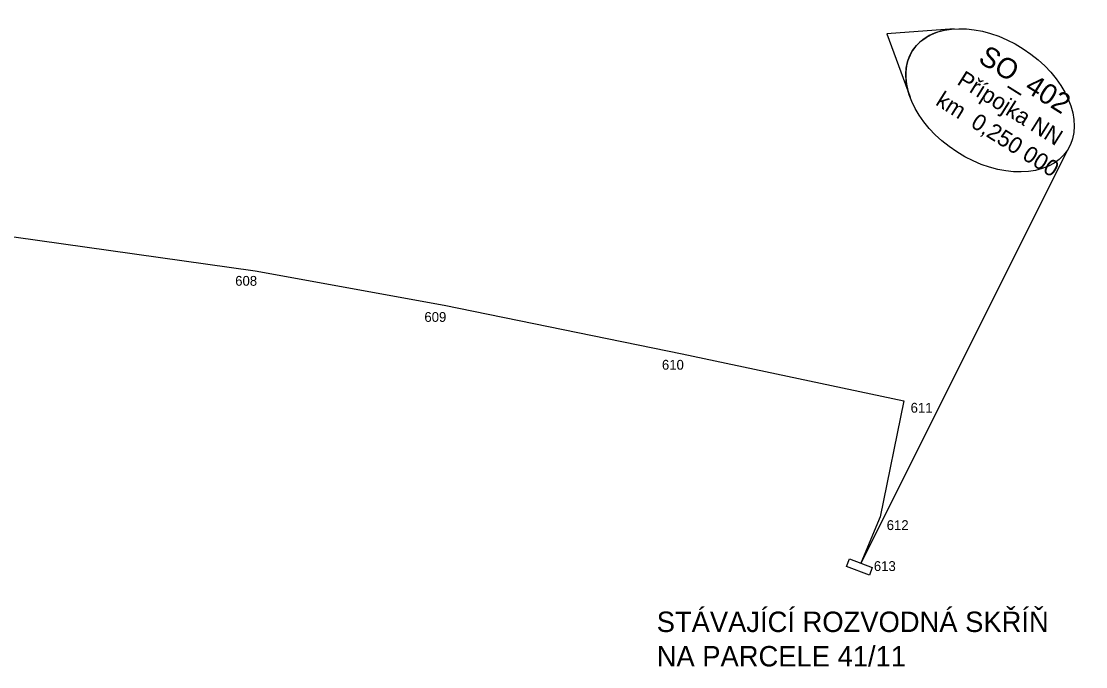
# Model space of a CAD drawing. Extents: x -743546 to -74, y -1128126 to -103.
# Drawn here: x -743045.6 to -742915.5, y -1127159.1 to -1127080.1 of the extents above; entities that cross this region are included whole.
import ezdxf

# ---------------------------------------------------------------- set-up
doc = ezdxf.new("R2010")
doc.units = 0
for name, color, linetype in [('_Násyp', 7, 'Continuous'), ('_TRASA_vedení kabelu_CEZ', 7, 'Continuous'), ('bublina_růžová_230_čára_tenká', 7, 'Continuous'), ('bublina_růžová_230_čára_tučná', 7, 'Continuous'), ('křížky', 7, 'Continuous'), ('Vrstva 60', 7, 'Continuous')]:
    doc.layers.add(name, color=color, linetype=linetype)

# ---------------------------------------------------------------- blocks, each defined once
blk = doc.blocks.new('POINT_DISPLAY')
blk.add_line((0, 0), (0, 0))

msp = doc.modelspace()

# ---------------------------------------------------------------- linework, layer by layer
at = {"layer": '_TRASA_vedení kabelu_CEZ'}
msp.add_lwpolyline([(-743154.26, -1127082.61), (-743159.25, -1127091.79), (-743078.98, -1127101.9), (-743017.04, -1127110.61), (-742993.93, -1127114.82), (-742964.82, -1127120.76), (-742937.74, -1127126.54), (-742940.65, -1127140.7), (-742943, -1127146.4)], dxfattribs=at)
msp.add_lwpolyline([(-742944.4, -1127145.87), (-742941.59, -1127146.92), (-742941.94, -1127147.86), (-742944.75, -1127146.81)], close=True, dxfattribs=at)
at = {"layer": 'bublina_růžová_230_čára_tenká'}
msp.add_line((-742917.74, -1127095.83), (-742943, -1127146.4), dxfattribs=at)
at = {"layer": 'bublina_růžová_230_čára_tučná'}
for p, q in [((-742931.59, -1127081.01), (-742939.82, -1127081.63)), ((-742931.59, -1127081.01), (-742939.82, -1127081.63)), ((-742939.82, -1127081.63), (-742936.98, -1127089.38)), ((-742939.82, -1127081.63), (-742936.98, -1127089.38))]:
    msp.add_line(p, q, dxfattribs=at)
msp.add_ellipse((-742927.2, -1127089.75), major_axis=(9.46, -6.09), ratio=0.666667, dxfattribs=at)
msp.add_ellipse((-742927.2, -1127089.75), major_axis=(-9.46, 6.09), ratio=0.666473, start_param=5.557317, end_param=7.009053, dxfattribs=at)
at = {"layer": 'Vrstva 60'}
for p, q in [((-743017.04, -1127110.61), (-743017.04, -1127110.61)), ((-742993.93, -1127114.82), (-742993.93, -1127114.82)), ((-742964.82, -1127120.76), (-742964.82, -1127120.76)), ((-742937.74, -1127126.54), (-742937.74, -1127126.54)), ((-742940.65, -1127140.7), (-742940.65, -1127140.7)), ((-742943, -1127146.4), (-742943, -1127146.4))]:
    msp.add_line(p, q, dxfattribs=at)

# ---------------------------------------------------------------- block references
at = {"layer": 'křížky', "xscale": 10, "yscale": 10, "rotation": 61.14491455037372}
for p in [(-743017.04, -1127110.61), (-742993.93, -1127114.82), (-742964.82, -1127120.76), (-742937.74, -1127126.54), (-742940.65, -1127140.7), (-742943, -1127146.4)]:
    msp.add_blockref('POINT_DISPLAY', p, dxfattribs=at)

# ---------------------------------------------------------------- texts
at = {"layer": '_Násyp'}
for s, height, p in [('SO_402', 2.5, (-742928.78, -1127085)), ('Přípojka NN', 2, (-742931.36, -1127087.72)), ('km  0,250 000', 2, (-742933.97, -1127090.23))]:
    msp.add_text(s, height=height, rotation=327.92, dxfattribs=at).set_placement(p)
at = {"layer": '_TRASA_vedení kabelu_CEZ'}
for s, p in [('STÁVAJÍCÍ ROZVODNÁ SKŘÍŇ ', (-742967.95, -1127154.81)), ('NA PARCELE 41/11', (-742967.95, -1127159.02))]:
    msp.add_text(s, height=2.5, dxfattribs=at).set_placement(p)
at = {"layer": 'Vrstva 60'}
for s, p in [('608', (-743019.48, -1127112.44)), ('609', (-742996.35, -1127116.86)), ('610', (-742967.31, -1127122.71)), ('611', (-742936.91, -1127127.97)), ('612', (-742939.83, -1127142.33)), ('613', (-742941.4, -1127147.34))]:
    msp.add_text(s, height=1.2, dxfattribs=at).set_placement(p)

doc.saveas('drawing.dxf')
